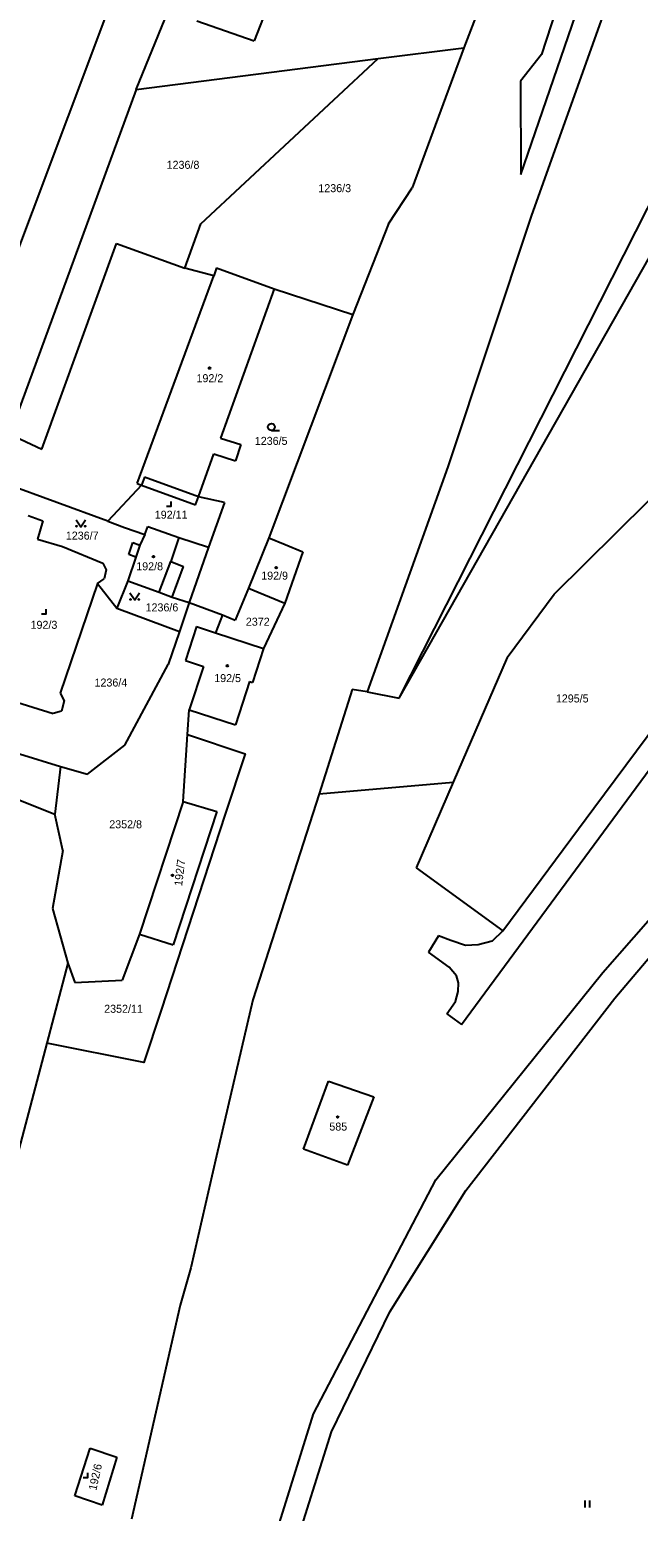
# Model space of a CAD drawing. Extents: x -717507 to -715515, y -957700 to -954941.
# Drawn here: x -716853.4 to -716724.1, y -957047 to -956732.3 of the extents above; entities that cross this region are included whole.
import ezdxf

# ---------------------------------------------------------------- set-up
doc = ezdxf.new("R2010")
doc.units = 0
for name, color, linetype in [('Hranice parcel', 7, 'Continuous'), ('Parcelní čísla', 7, 'Continuous'), ('Vnitřní kresba', 7, 'Continuous'), ('Značky budov', 7, 'Continuous'), ('Značky kultur', 7, 'Continuous')]:
    doc.layers.add(name, color=color, linetype=linetype)

msp = doc.modelspace()

# ---------------------------------------------------------------- linework, layer by layer
at = {"layer": 'Hranice parcel'}
for points in [[(-716860.64, -956791.7), (-716822.01, -956689.04)], [(-716745.76, -956695.95), (-716761.17, -956736.13)], [(-716774.89, -956874.26), (-716692.04, -956710.7)], [(-716774.89, -956874.26), (-716682.29, -956710.93)], [(-716749.07, -956763.08), (-716733.61, -956717.87)], [(-716738.52, -956718.59), (-716744.66, -956737.58)], [(-716801.36, -956723.58), (-716805.72, -956734.66)], [(-716830.72, -956744.98), (-716823.98, -956728.33)], [(-716817.87, -956730.4), (-716805.72, -956734.66)], [(-716731.71, -956729.53), (-716746.79, -956771.67)], [(-716779.36, -956738.45), (-716761.17, -956736.13)], [(-716761.17, -956736.13), (-716772.13, -956765.86)], [(-716744.66, -956737.58), (-716749.17, -956743.25)], [(-716830.72, -956744.98), (-716779.36, -956738.45)], [(-716817.03, -956773.53), (-716779.36, -956738.45)], [(-716749.17, -956743.25), (-716749.07, -956763.08)], [(-716830.72, -956744.98), (-716857.59, -956818.19)], [(-716777.14, -956773.56), (-716772.13, -956765.86)], [(-716746.79, -956771.67), (-716764.58, -956825.12)], [(-716820.44, -956782.94), (-716817.03, -956773.53)], [(-716777.14, -956773.56), (-716784.72, -956792.81)], [(-716850.81, -956821.41), (-716834.94, -956777.73)], [(-716834.94, -956777.73), (-716820.44, -956782.94)], [(-716814.25, -956784.61), (-716820.44, -956782.94)], [(-716813.7, -956782.9), (-716814.25, -956784.61)], [(-716813.7, -956782.9), (-716801.43, -956787.31)], [(-716801.43, -956787.31), (-716812.84, -956819.05)], [(-716801.43, -956787.31), (-716784.72, -956792.81)], [(-716784.72, -956792.81), (-716802.56, -956840.25)], [(-716857.59, -956818.19), (-716850.81, -956821.41)], [(-716812.84, -956819.05), (-716808.56, -956820.38)], [(-716817.5, -956831.53), (-716814.23, -956822.41)], [(-716814.23, -956822.41), (-716809.64, -956823.91)], [(-716808.56, -956820.38), (-716809.64, -956823.91)], [(-716764.58, -956825.12), (-716781.68, -956872.97)], [(-716742.01, -956852.17), (-716715.4, -956825.86)], [(-716836.76, -956836.72), (-716858.43, -956828.76)], [(-716828.97, -956827.37), (-716829.58, -956829.06)], [(-716817.5, -956831.53), (-716828.97, -956827.37)], [(-716829.58, -956829.06), (-716836.76, -956836.72)], [(-716812.02, -956832.7), (-716817.5, -956831.53)], [(-716812.02, -956832.7), (-716815.38, -956842.2)], [(-716853.71, -956835.49), (-716850.57, -956836.62)], [(-716850.57, -956836.62), (-716851.67, -956840.53)], [(-716836.76, -956836.72), (-716833.2, -956838.02)], [(-716833.2, -956838.02), (-716828.94, -956839.53)], [(-716828.94, -956839.53), (-716828.29, -956837.83)], [(-716828.29, -956837.83), (-716821.66, -956840.17)], [(-716851.67, -956840.53), (-716846.4, -956842.04)], [(-716832.33, -956843.77), (-716831.43, -956841.25)], [(-716831.43, -956841.25), (-716829.95, -956841.8)], [(-716828.94, -956839.53), (-716829.95, -956841.8)], [(-716821.66, -956840.17), (-716823.36, -956845.26)], [(-716802.56, -956840.25), (-716806.93, -956850.92)], [(-716802.56, -956840.25), (-716799.1, -956841.68)], [(-716846.4, -956842.04), (-716837.82, -956845.6)], [(-716830.83, -956844.34), (-716832.55, -956849.35)], [(-716830.83, -956844.34), (-716832.33, -956843.77)], [(-716815.38, -956842.2), (-716819.5, -956853.99)], [(-716795.33, -956843.23), (-716799.21, -956854.08)], [(-716799.1, -956841.68), (-716795.33, -956843.23)], [(-716837.82, -956845.6), (-716837.14, -956847.05)], [(-716837.14, -956847.05), (-716837.57, -956848.94)], [(-716823.36, -956845.26), (-716820.71, -956846.31)], [(-716823.11, -956852.85), (-716820.71, -956846.31)], [(-716838.98, -956849.93), (-716846.91, -956873.25)], [(-716838.98, -956849.93), (-716837.57, -956848.94)], [(-716838.98, -956849.93), (-716834.88, -956855.15)], [(-716832.55, -956849.35), (-716834.88, -956855.15)], [(-716832.55, -956849.35), (-716825.88, -956851.81)], [(-716806.93, -956850.92), (-716809.7, -956857.69)], [(-716806.93, -956850.92), (-716799.21, -956854.08)], [(-716733.6, -956897.64), (-716697.16, -956848.67)], [(-716825.88, -956851.81), (-716823.11, -956852.85)], [(-716823.11, -956852.85), (-716819.5, -956853.99)], [(-716819.5, -956853.99), (-716821.56, -956860.1)], [(-716819.5, -956853.99), (-716812.42, -956856.61)], [(-716799.21, -956854.08), (-716803.7, -956863.72)], [(-716751.98, -956865.63), (-716742.01, -956852.17)], [(-716834.88, -956855.15), (-716821.56, -956860.1)], [(-716812.42, -956856.61), (-716813.89, -956860.4)], [(-716812.42, -956856.61), (-716809.7, -956857.69)], [(-716821.56, -956860.1), (-716823.96, -956867.16)], [(-716817.96, -956859.07), (-716820.3, -956866.29)], [(-716817.96, -956859.07), (-716813.89, -956860.4)], [(-716813.89, -956860.4), (-716803.7, -956863.72)], [(-716820.3, -956866.29), (-716816.46, -956867.54)], [(-716803.7, -956863.72), (-716806.03, -956870.94)], [(-716751.98, -956865.63), (-716763.41, -956892.14)], [(-716833.12, -956884.24), (-716823.96, -956867.16)], [(-716816.46, -956867.54), (-716819.47, -956876.8)], [(-716864.61, -956872.51), (-716848.38, -956877.58)], [(-716806.67, -956870.73), (-716809.64, -956879.99)], [(-716806.67, -956870.73), (-716806.03, -956870.94)], [(-716784.87, -956872.43), (-716791.91, -956894.64)], [(-716781.68, -956872.97), (-716784.87, -956872.43)], [(-716781.68, -956872.97), (-716774.89, -956874.26)], [(-716846.91, -956873.25), (-716846, -956874.83)], [(-716846, -956874.83), (-716846.61, -956877.03)], [(-716846.61, -956877.03), (-716848.38, -956877.58)], [(-716819.83, -956882.04), (-716819.47, -956876.8)], [(-716819.47, -956876.8), (-716809.64, -956879.99)], [(-716873.03, -956880.76), (-716846.8, -956888.82)], [(-716819.83, -956882.04), (-716807.62, -956886.1), (-716811.82, -956898.96), (-716825.43, -956940.57), (-716829.09, -956951.65), (-716849.73, -956947.55)], [(-716820.8, -956896.26), (-716819.83, -956882.04)], [(-716841.06, -956890.47), (-716833.12, -956884.24)], [(-716875.96, -956887.84), (-716848.02, -956898.9)], [(-716846.8, -956888.82), (-716848.02, -956898.9)], [(-716846.8, -956888.82), (-716841.06, -956890.47)], [(-716732.5, -956904.02), (-716720.61, -956887.89)], [(-716791.91, -956894.64), (-716805.96, -956938.36)], [(-716791.91, -956894.64), (-716763.41, -956892.14)], [(-716763.41, -956892.14), (-716771.27, -956910.36)], [(-716731.68, -956932.56), (-716698.73, -956895.06)], [(-716820.8, -956896.26), (-716830.05, -956924.41)], [(-716820.8, -956896.26), (-716813.6, -956898.38)], [(-716752.91, -956923.68), (-716733.6, -956897.64)], [(-716846.31, -956906.64), (-716848.02, -956898.9)], [(-716813.6, -956898.38), (-716822.88, -956926.67)], [(-716761.68, -956943.6), (-716732.5, -956904.02)], [(-716846.31, -956906.64), (-716848.51, -956918.97)], [(-716771.27, -956910.36), (-716752.91, -956923.68)], [(-716729.15, -956938.03), (-716708.83, -956914)], [(-716848.51, -956918.97), (-716845.27, -956930.57)], [(-716830.05, -956924.41), (-716833.73, -956934.18)], [(-716830.05, -956924.41), (-716822.88, -956926.67)], [(-716766.57, -956924.81), (-716768.66, -956928.22)], [(-716763.95, -956925.77), (-716766.57, -956924.81)], [(-716760.83, -956926.82), (-716763.95, -956925.77)], [(-716755.19, -956925.94), (-716758.16, -956926.69)], [(-716752.91, -956923.68), (-716755.19, -956925.94)], [(-716764.27, -956931.42), (-716768.66, -956928.22)], [(-716758.16, -956926.69), (-716760.83, -956926.82)], [(-716845.27, -956930.57), (-716849.73, -956947.55)], [(-716845.27, -956930.57), (-716843.78, -956934.72)], [(-716767.1, -956976.62), (-716731.68, -956932.56)], [(-716762.74, -956933.25), (-716764.27, -956931.42)], [(-716843.78, -956934.72), (-716833.73, -956934.18)], [(-716762.32, -956934.75), (-716762.74, -956933.25)], [(-716762.37, -956936.6), (-716762.32, -956934.75)], [(-716805.96, -956938.36), (-716813.7, -956971.5)], [(-716764.8, -956941.34), (-716762.94, -956938.72)], [(-716762.94, -956938.72), (-716762.37, -956936.6)], [(-716760.73, -956978.86), (-716729.15, -956938.03)], [(-716764.8, -956941.34), (-716761.68, -956943.6)], [(-716849.73, -956947.55), (-716858.15, -956979.57)], [(-716795.23, -956970.12), (-716789.9, -956955.65)], [(-716789.9, -956955.65), (-716780.28, -956959)], [(-716780.28, -956959), (-716785.89, -956973.5)], [(-716785.89, -956973.5), (-716795.23, -956970.12)], [(-716813.7, -956971.5), (-716819.13, -956995.27)], [(-716793.1, -957026.3), (-716767.1, -956976.62)], [(-716776.9, -957004.61), (-716760.73, -956978.86)], [(-716819.13, -956995.27), (-716821.44, -957003.26)], [(-716821.44, -957003.26), (-716831.73, -957048.65)], [(-716789.3, -957030.13), (-716776.9, -957004.61)], [(-716807.86, -957073.78), (-716793.1, -957026.3)], [(-716800.35, -957065.24), (-716789.3, -957030.13)], [(-716843.74, -957043.76), (-716840.51, -957033.63)], [(-716840.51, -957033.63), (-716834.85, -957035.54)], [(-716834.85, -957035.54), (-716837.97, -957045.73)], [(-716837.97, -957045.73), (-716843.74, -957043.76)]]:
    msp.add_lwpolyline(points, dxfattribs=at)
at = {"layer": 'Vnitřní kresba'}
for points in [[(-716830.53, -956828.71), (-716814.25, -956784.61)], [(-716830.53, -956828.71), (-716829.58, -956829.06)], [(-716829.58, -956829.06), (-716818.13, -956833.25)], [(-716818.13, -956833.25), (-716817.5, -956831.53)], [(-716821.66, -956840.17), (-716815.38, -956842.2)], [(-716829.95, -956841.8), (-716830.83, -956844.34)], [(-716825.88, -956851.81), (-716823.36, -956845.26)]]:
    msp.add_lwpolyline(points, dxfattribs=at)
at = {"layer": 'Značky budov'}
for centre in [(-716815.17, -956804.18), (-716827.08, -956844.22), (-716801.01, -956846.57), (-716811.38, -956867.41), (-716823.04, -956911.94), (-716787.97, -956963.27)]:
    msp.add_circle(centre, 0.175, dxfattribs=at)
at = {"layer": 'Značky kultur'}
for points in [[(-716802.04, -956817.44), (-716800.29, -956817.44)], [(-716824.29, -956833.54), (-716823.29, -956833.54), (-716823.29, -956832.54)], [(-716843.49, -956836.39), (-716842.49, -956837.89), (-716841.49, -956836.39)], [(-716832.06, -956851.9), (-716831.06, -956853.4), (-716830.06, -956851.9)], [(-716850.84, -956856.41), (-716849.84, -956856.41), (-716849.84, -956855.41)], [(-716841.99, -957039.83), (-716840.99, -957039.83), (-716840.99, -957038.83)], [(-716735.44, -957046.19), (-716735.44, -957044.69)], [(-716734.4, -957046.19), (-716734.4, -957044.69)]]:
    msp.add_lwpolyline(points, dxfattribs=at)
for centre, radius in [((-716802.04, -956816.69), 0.75), ((-716843.39, -956837.79), 0.1), ((-716841.59, -956837.79), 0.1), ((-716831.96, -956853.3), 0.1), ((-716830.16, -956853.3), 0.1)]:
    msp.add_circle(centre, radius, dxfattribs=at)

# ---------------------------------------------------------------- texts
at = {"layer": 'Parcelní čísla'}
for s, p in [('1236/8', (-716824.28, -956761.85)), ('1236/3', (-716792.07, -956766.81)), ('192/2', (-716817.94, -956807.17)), ('1236/5', (-716805.56, -956820.49)), ('192/11', (-716826.8, -956836.17)), ('1236/7', (-716845.68, -956840.61)), ('192/8', (-716830.73, -956847.13)), ('192/9', (-716804.2, -956849.12)), ('1236/6', (-716828.75, -956855.86)), ('2372', (-716807.46, -956858.9)), ('192/3', (-716853.17, -956859.56)), ('192/5', (-716814.18, -956870.88)), ('1236/4', (-716839.59, -956871.82)), ('1295/5', (-716741.64, -956875.2)), ('2352/8', (-716836.46, -956901.93)), ('2352/11', (-716837.54, -956941.12)), ('585', (-716789.73, -956966.14))]:
    msp.add_text(s, height=1.7, dxfattribs=at).set_placement(p)
for s, rotation, p in [('192/7', 83.1007, (-716821, -956914.27)), ('192/6', 77.4006, (-716839.22, -957042.69))]:
    msp.add_text(s, height=1.7, rotation=rotation, dxfattribs=at).set_placement(p)

doc.saveas('drawing.dxf')
